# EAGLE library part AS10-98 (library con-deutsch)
DEUTSCH Connector
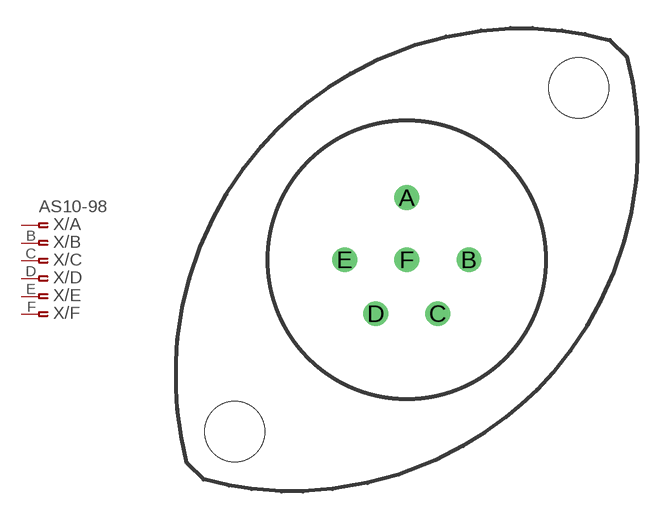
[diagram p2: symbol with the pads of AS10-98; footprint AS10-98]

Designator prefix X; gates /A=PINF_VAL /B=ASPINF /C=ASPINF /D=ASPINF /E=ASPINF /F=ASPINF

## AS10-98 (OC_FARNELL: unknown; OC_NEWARK: unknown)  [AS10-98]
A  /A:1  pas
B  /B:1  pas
C  /C:1  pas
D  /D:1  pas
E  /E:1  pas
F  /F:1  pas

## Footprint AS10-98 (pad centres in mm)
DEUTSCH Connector
drill 0.813 round: A 0,3.302; B 3.302,0; C 1.651,-2.87; D -1.651,-2.87; E -3.302,0; F 0,0
hole 3.2 at 9.144,9.144
hole 3.2 at -9.144,-9.144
